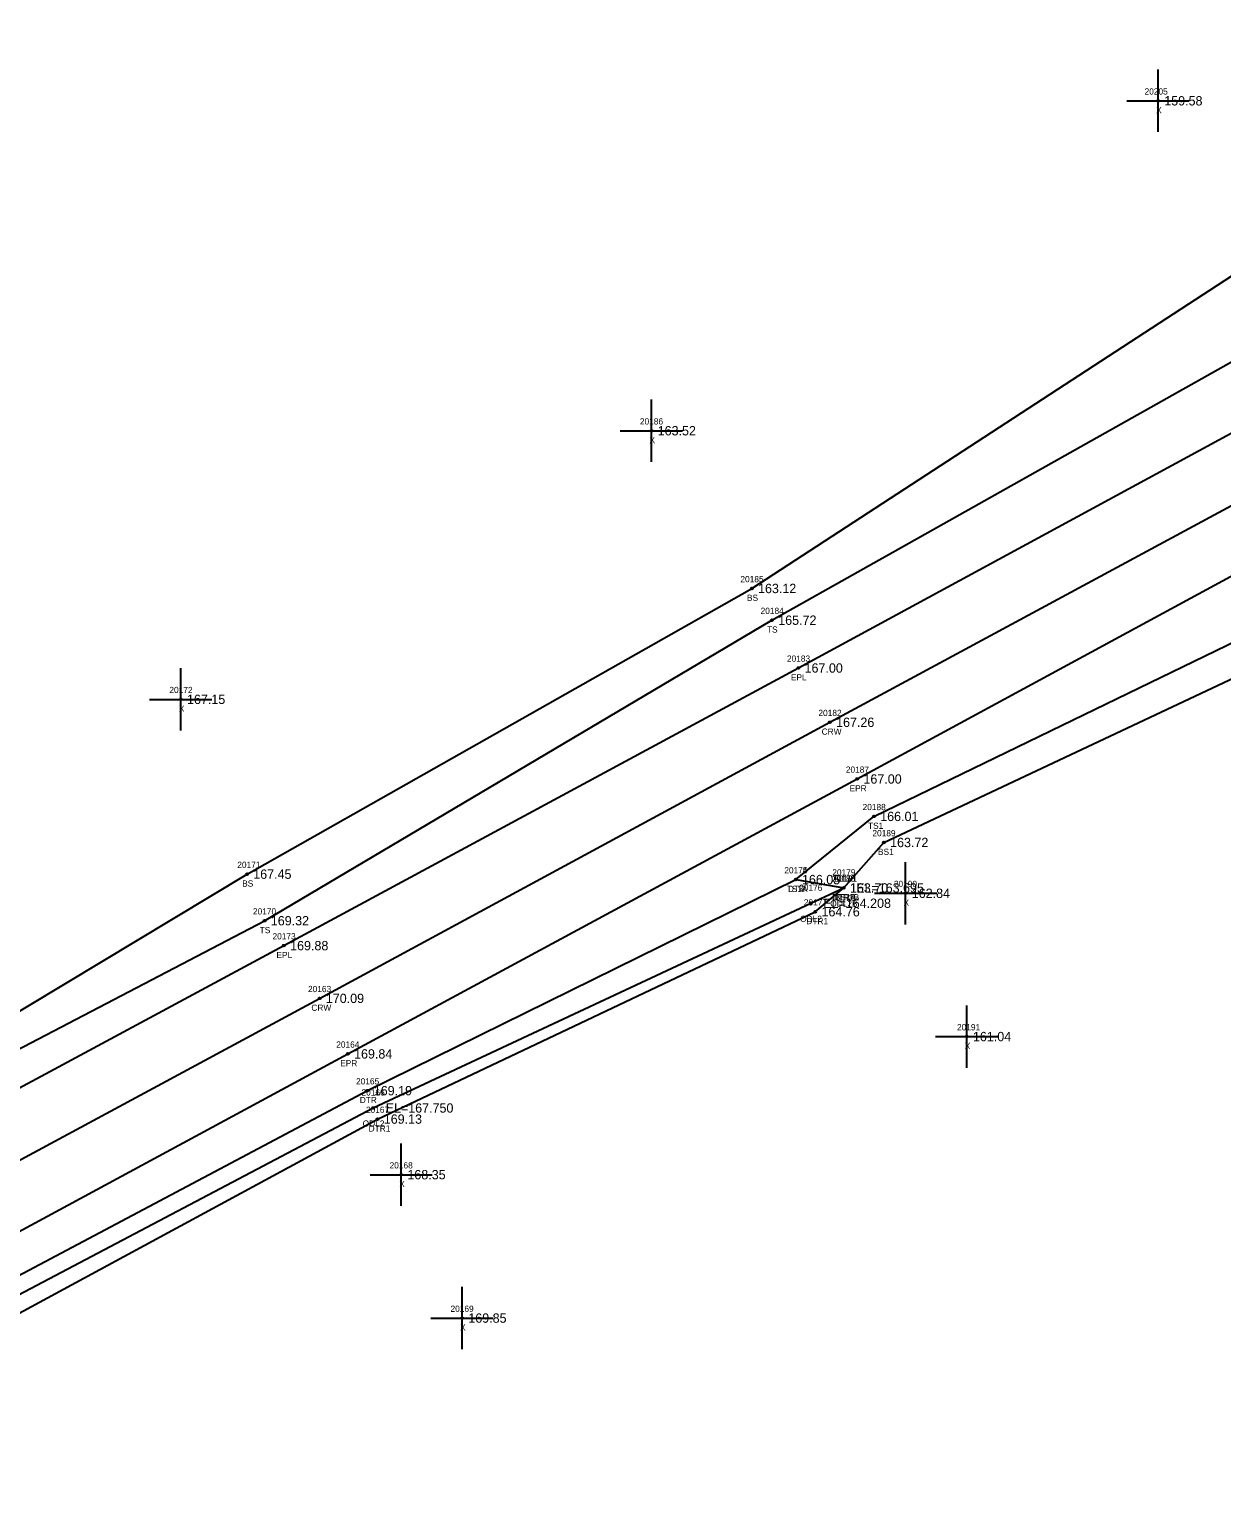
# Model space of a CAD drawing. Extents: x 2279528 to 2280976, y 1061373 to 1062235.
# Drawn here: x 2279936.3 to 2280127.5, y 1061580.4 to 1061818 of the extents above; entities that cross this region are included whole.
import ezdxf

# ---------------------------------------------------------------- set-up
doc = ezdxf.new("R2010")
doc.units = 0
for name, color, linetype in [('RD_DTM_BkLn1', 7, 'Continuous'), ('RD_DTM_BkLn2', 7, 'Continuous'), ('RD_DTM_BkLn_txCode', 7, 'Continuous'), ('RD_EX_H2O', 7, 'Continuous'), ('RD_EX_H2O_txCode', 7, 'Continuous'), ('RD_EX_Misc', 7, 'Continuous'), ('RD_EX_Misc_txCode', 7, 'Continuous'), ('RD_EX_Road', 7, 'Continuous'), ('RD_EX_Road_txCode', 7, 'Continuous'), ('RD_EX_TX_H2O_ELEV', 7, 'Continuous'), ('RD_EX_TX_Misc_ELEV', 7, 'Continuous'), ('RD_EX_TX_Road_ELEV', 7, 'Continuous'), ('RD_HC_Survey_ELEV', 7, 'Continuous'), ('RD_HC_Survey_txCode', 7, 'Continuous'), ('RD_SMD_Locator', 7, 'Continuous')]:
    doc.layers.add(name, color=color, linetype=linetype)

msp = doc.modelspace()

# ---------------------------------------------------------------- linework, layer by layer
at = {"layer": 'RD_DTM_BkLn1'}
msp.add_lwpolyline([(2279559.79, 1061433.13), (2279641.23, 1061477.49), (2279727.93, 1061524.84), (2279814.76, 1061571.75), (2279901.26, 1061618.64), (2279982.8, 1061662.56), (2280064.7, 1061706.86), (2280148.08, 1061751.86), (2280234.22, 1061798.46), (2280310.96, 1061840.01), (2280397.69, 1061887.57), (2280487.27, 1061936.5), (2280573.03, 1061983.12), (2280654.64, 1062027.66), (2280741.28, 1062074.45), (2280833.39, 1062123.87), (2280892.52, 1062155.9), (2280939.46, 1062181.85)], dxfattribs=at)
at = {"layer": 'RD_DTM_BkLn2'}
for points in [[(2279912.54, 1061647.23), (2279971.15, 1061682.49), (2280052.17, 1061728.33), (2280132.75, 1061780.82), (2280164.61, 1061792.77), (2280185.62, 1061809.36)], [(2279918.28, 1061645.97), (2279973.97, 1061675.02), (2280055.41, 1061723.24), (2280139.04, 1061770.27), (2280166.79, 1061783.8), (2280197.35, 1061795.14), (2280211.16, 1061800.79)], [(2280059.22, 1061681.62), (2280071.78, 1061691.76), (2280158.6, 1061733.81), (2280171.38, 1061740.74), (2280178.6, 1061748.25), (2280197.42, 1061760.44), (2280219.45, 1061768.68)], [(2280066.92, 1061680.28), (2280073.37, 1061687.57), (2280161.47, 1061729), (2280173.75, 1061738.9), (2280180.46, 1061744.56), (2280207.84, 1061753.79), (2280214.1, 1061757.73), (2280223.01, 1061764.94)]]:
    msp.add_lwpolyline(points, dxfattribs=at)
at = {"layer": 'RD_EX_H2O'}
for points in [[(2279876.74, 1061587.42), (2279908.82, 1061604.49), (2279990.5, 1061647.75), (2280059.22, 1061681.62), (2280066.92, 1061680.28)], [(2279876.74, 1061587.42), (2279878.88, 1061584.25), (2279911.31, 1061599.46), (2279992.1, 1061643.19), (2280062.36, 1061676.46), (2280066.92, 1061680.28)], [(2279880.37, 1061587.13), (2279909.85, 1061602.05), (2279991.4, 1061644.97), (2280061.63, 1061677.82), (2280066.92, 1061680.28)]]:
    msp.add_lwpolyline(points, dxfattribs=at)
at = {"layer": 'RD_EX_Misc'}
for p, q in [((2280117.37, 1061801.58), (2280117.37, 1061811.58)), ((2280112.37, 1061806.58), (2280122.37, 1061806.58)), ((2280036.06, 1061748.64), (2280036.06, 1061758.64)), ((2280031.06, 1061753.64), (2280041.06, 1061753.64)), ((2279960.52, 1061705.54), (2279960.52, 1061715.54)), ((2279955.52, 1061710.54), (2279965.52, 1061710.54)), ((2280076.85, 1061674.42), (2280076.85, 1061684.42)), ((2280071.85, 1061679.42), (2280081.85, 1061679.42)), ((2280086.66, 1061651.43), (2280086.66, 1061661.43)), ((2280081.66, 1061656.43), (2280091.66, 1061656.43)), ((2279995.89, 1061629.27), (2279995.89, 1061639.27)), ((2279990.89, 1061634.27), (2280000.89, 1061634.27)), ((2280005.67, 1061606.26), (2280005.67, 1061616.26)), ((2280000.67, 1061611.26), (2280010.67, 1061611.26))]:
    msp.add_line(p, q, dxfattribs=at)
at = {"layer": 'RD_EX_Road'}
for points in [[(2279554.31, 1061441.46), (2279636.61, 1061486.51), (2279673.46, 1061506.76), (2279683.06, 1061512.21), (2279723.14, 1061533.54), (2279809.28, 1061580.29), (2279896.91, 1061627.91), (2279977.07, 1061671.02), (2280059.64, 1061715.57), (2280142.91, 1061760.72), (2280228.83, 1061807.06), (2280306.04, 1061849.18), (2280392.98, 1061896.71), (2280482.82, 1061945.75), (2280567.83, 1061991.78), (2280649.94, 1062036.55), (2280660.56, 1062042.19), (2280676.12, 1062050.66), (2280737.28, 1062083.64), (2280828.54, 1062132.77), (2280887.86, 1062164.61), (2280934.91, 1062190.9)], [(2279906, 1061609.76), (2279987.33, 1061653.65), (2280069.09, 1061697.76), (2280153.19, 1061743.35), (2280194.51, 1061765.35), (2280202.82, 1061771.34), (2280211.47, 1061775.32), (2280215.93, 1061780.7), (2280225.22, 1061785.77), (2280231.78, 1061787.38), (2280251.88, 1061797.82), (2280255.66, 1061801.36), (2280256.83, 1061804.75), (2280266.2, 1061806.83), (2280270.78, 1061807.29), (2280284.33, 1061814.31), (2280315.09, 1061831.32), (2280403.05, 1061879.04), (2280492, 1061927.92)]]:
    msp.add_lwpolyline(points, dxfattribs=at)
at = {"layer": 'RD_SMD_Locator'}
for centre in [(2280117.37, 1061806.58), (2280036.06, 1061753.64), (2280052.17, 1061728.33), (2280055.41, 1061723.24), (2280059.64, 1061715.57), (2279960.52, 1061710.54), (2280064.7, 1061706.86), (2280069.09, 1061697.76), (2280071.78, 1061691.76), (2280073.37, 1061687.57), (2279971.15, 1061682.49), (2280059.22, 1061681.62), (2280059.22, 1061681.62), (2280066.92, 1061680.28), (2280066.92, 1061680.28), (2280066.92, 1061680.28), (2280066.92, 1061680.28), (2280061.63, 1061677.82), (2280076.85, 1061679.42), (2279973.97, 1061675.02), (2280062.36, 1061676.46), (2279977.07, 1061671.02), (2279982.8, 1061662.56), (2280086.66, 1061656.43), (2279987.33, 1061653.65), (2279990.5, 1061647.75), (2279991.4, 1061644.97), (2279992.1, 1061643.19), (2279995.89, 1061634.27), (2280005.67, 1061611.26)]:
    msp.add_circle(centre, 0.15, dxfattribs=at)

# ---------------------------------------------------------------- texts
at = {"layer": 'RD_DTM_BkLn_txCode'}
for s, p in [('20185', (2280050.34, 1061729.33)), ('BS', (2280051.39, 1061726.33)), ('20184', (2280053.58, 1061724.24)), ('TS', (2280054.61, 1061721.24)), ('20188', (2280069.95, 1061692.76)), ('TS1', (2280070.82, 1061689.76)), ('20189', (2280071.53, 1061688.57)), ('20171', (2279969.59, 1061683.49)), ('BS1', (2280072.42, 1061685.57)), ('20174', (2280057.39, 1061682.62)), ('20181', (2280065.37, 1061681.28)), ('BS', (2279970.37, 1061680.49)), ('TS1A', (2280057.77, 1061679.62)), ('BS1A', (2280065.49, 1061678.28)), ('20170', (2279972.1, 1061676.02)), ('TS', (2279973.18, 1061673.02))]:
    msp.add_text(s, height=1, dxfattribs=at).set_placement(p)
at = {"layer": 'RD_EX_H2O_txCode'}
for s, p in [('20175', (2280057.39, 1061682.62)), ('20180', (2280065.05, 1061681.28)), ('20179', (2280065.09, 1061682.28)), ('20178', (2280065.09, 1061681.28)), ('DTR', (2280057.95, 1061679.62)), ('20176', (2280059.77, 1061679.82)), ('20177', (2280060.52, 1061677.46)), ('ODL2B', (2280064.76, 1061677.28)), ('DTR1B', (2280065.02, 1061678.28)), ('DTRB', (2280065.18, 1061678.28)), ('ODL2', (2280059.93, 1061674.82)), ('DTR1', (2280060.92, 1061674.46)), ('20165', (2279988.65, 1061648.75)), ('DTR', (2279989.24, 1061645.75)), ('20166', (2279989.52, 1061646.97)), ('20167', (2279990.24, 1061644.19)), ('ODL2', (2279989.71, 1061641.97)), ('DTR1', (2279990.67, 1061641.19))]:
    msp.add_text(s, height=1, dxfattribs=at).set_placement(p)
at = {"layer": 'RD_EX_Misc_txCode'}
for s, p in [('20205', (2280115.21, 1061807.58)), ('X', (2280117.06, 1061804.58)), ('20186', (2280034.21, 1061754.64)), ('X', (2280035.75, 1061751.64)), ('20172', (2279958.69, 1061711.54)), ('X', (2279960.21, 1061708.54)), ('20190', (2280074.97, 1061680.42)), ('X', (2280076.53, 1061677.42)), ('20191', (2280085.11, 1061657.43)), ('X', (2280086.35, 1061654.43)), ('20168', (2279994.03, 1061635.27)), ('X', (2279995.58, 1061632.27)), ('20169', (2280003.81, 1061612.26)), ('X', (2280005.35, 1061609.26))]:
    msp.add_text(s, height=1, dxfattribs=at).set_placement(p)
at = {"layer": 'RD_EX_Road_txCode'}
for s, p in [('20183', (2280057.81, 1061716.57)), ('EPL', (2280058.44, 1061713.57)), ('20187', (2280067.26, 1061698.76)), ('EPR', (2280067.86, 1061695.76)), ('20173', (2279975.24, 1061672.02)), ('EPL', (2279975.87, 1061669.02)), ('20164', (2279985.47, 1061654.65)), ('EPR', (2279986.1, 1061651.65))]:
    msp.add_text(s, height=1, dxfattribs=at).set_placement(p)
at = {"layer": 'RD_EX_TX_H2O_ELEV'}
for s, p in [('166.05', (2280060.22, 1061680.87)), ('163.70', (2280067.92, 1061679.53)), ('163.70', (2280067.92, 1061679.53)), ('EL=163.695', (2280068.92, 1061679.53)), ('EL=164.208', (2280063.63, 1061677.07)), ('164.76', (2280063.36, 1061675.71)), ('169.19', (2279991.5, 1061647)), ('EL=167.750', (2279993.4, 1061644.22)), ('169.13', (2279993.1, 1061642.44))]:
    msp.add_text(s, height=1.5, dxfattribs=at).set_placement(p)
at = {"layer": 'RD_EX_TX_Misc_ELEV'}
for s, p in [('159.58', (2280118.37, 1061805.83)), ('163.52', (2280037.06, 1061752.89)), ('163.12', (2280053.17, 1061727.58)), ('165.72', (2280056.41, 1061722.49)), ('167.15', (2279961.52, 1061709.79)), ('166.01', (2280072.78, 1061691.01)), ('163.72', (2280074.37, 1061686.82)), ('167.45', (2279972.15, 1061681.74)), ('166.05', (2280060.22, 1061680.87)), ('163.70', (2280067.92, 1061679.53)), ('162.84', (2280077.85, 1061678.67)), ('169.32', (2279974.97, 1061674.27)), ('161.04', (2280087.66, 1061655.68)), ('168.35', (2279996.89, 1061633.52)), ('169.85', (2280006.67, 1061610.51))]:
    msp.add_text(s, height=1.5, dxfattribs=at).set_placement(p)
at = {"layer": 'RD_EX_TX_Road_ELEV'}
for s, p in [('167.00', (2280060.64, 1061714.82)), ('167.00', (2280070.09, 1061697.01)), ('169.88', (2279978.07, 1061670.27)), ('169.84', (2279988.33, 1061652.9))]:
    msp.add_text(s, height=1.5, dxfattribs=at).set_placement(p)
at = {"layer": 'RD_HC_Survey_ELEV'}
for s, p in [('167.26', (2280065.7, 1061706.11)), ('170.09', (2279983.8, 1061661.81))]:
    msp.add_text(s, height=1.5, dxfattribs=at).set_placement(p)
at = {"layer": 'RD_HC_Survey_txCode'}
for s, p in [('20182', (2280062.86, 1061707.86)), ('CRW', (2280063.38, 1061704.86)), ('20163', (2279980.94, 1061663.56)), ('CRW', (2279981.48, 1061660.56))]:
    msp.add_text(s, height=1, dxfattribs=at).set_placement(p)

doc.saveas('drawing.dxf')
